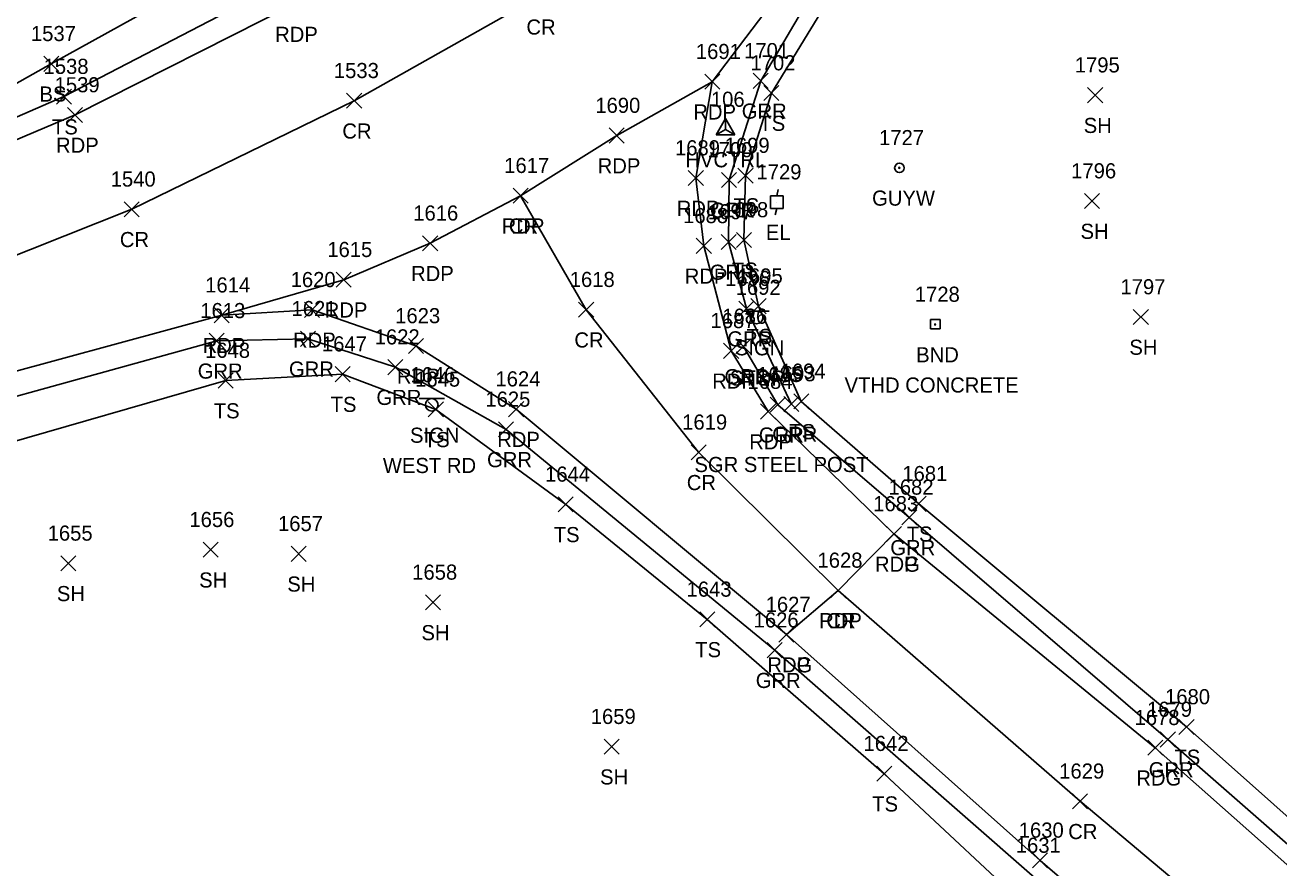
# Model space of a CAD drawing. Extents: x 1629176 to 1637209, y 606063 to 610167.
# Drawn here: x 1629782.2 to 1629948.1, y 606728.3 to 606839.8 of the extents above; entities that cross this region are included whole.
import ezdxf

# ---------------------------------------------------------------- set-up
doc = ezdxf.new("R2010")
doc.units = 0
for name, color, linetype in [('C_A', 7, 'Continuous'), ('C_I', 7, 'Continuous'), ('CPSM', 7, 'Continuous'), ('L_A', 7, 'Continuous'), ('L_I', 7, 'Continuous'), ('L_TIC', 7, 'Continuous'), ('LELB', 7, 'Continuous'), ('M_A', 7, 'Continuous'), ('M_C', 7, 'Continuous'), ('M_I', 7, 'Continuous'), ('MHBP', 7, 'Continuous'), ('P_A', 7, 'Continuous'), ('P_I', 7, 'Continuous'), ('P_TIC', 7, 'Continuous'), ('PET', 7, 'Continuous'), ('PEU', 7, 'Continuous'), ('PRC', 7, 'Continuous'), ('R_A', 7, 'Continuous'), ('R_C', 7, 'Continuous'), ('R_I', 7, 'Continuous'), ('R_TIC', 7, 'Continuous'), ('RGR', 7, 'Continuous'), ('S_A', 7, 'Continuous'), ('S_C', 7, 'Continuous'), ('S_I', 7, 'Continuous'), ('SSGN', 7, 'Continuous'), ('U_A', 7, 'Continuous'), ('U_I', 7, 'Continuous'), ('UEPT', 7, 'Continuous'), ('UPGW', 7, 'Continuous')]:
    doc.layers.add(name, color=color, linetype=linetype)

msp = doc.modelspace()

# ---------------------------------------------------------------- linework, layer by layer
at = {"layer": 'CPSM'}
for p, q in [((1629873.61, 606825.25), (1629874.86, 606827.42)), ((1629876.11, 606825.25), (1629874.86, 606827.42)), ((1629874.86, 606825.97), (1629874.86, 606827.42)), ((1629873.61, 606825.25), (1629874.86, 606825.97)), ((1629873.61, 606825.25), (1629876.11, 606825.25)), ((1629874.86, 606825.97), (1629874.86, 606825.97)), ((1629874.86, 606825.97), (1629876.11, 606825.25))]:
    msp.add_line(p, q, dxfattribs=at)
at = {"layer": 'L_TIC'}
for points in [[(1629784.68, 606833.66), (1629786.68, 606835.66)], [(1629786.68, 606833.66), (1629784.68, 606835.66)], [(1629786.36, 606829.32), (1629788.36, 606831.32)], [(1629788.36, 606829.32), (1629786.36, 606831.32)], [(1629879.93, 606829.79), (1629881.93, 606831.79)], [(1629881.93, 606829.79), (1629879.93, 606831.79)], [(1629922.75, 606829.51), (1629924.75, 606831.51)], [(1629924.75, 606829.51), (1629922.75, 606831.51)], [(1629876.5, 606818.88), (1629878.5, 606820.88)], [(1629878.5, 606818.88), (1629876.5, 606820.88)], [(1629922.33, 606815.51), (1629924.33, 606817.51)], [(1629924.33, 606815.51), (1629922.33, 606817.51)], [(1629876.3, 606810.37), (1629878.3, 606812.37)], [(1629878.3, 606810.37), (1629876.3, 606812.37)], [(1629878.22, 606801.61), (1629880.22, 606803.61)], [(1629880.22, 606801.61), (1629878.22, 606803.61)], [(1629928.79, 606800.18), (1629930.79, 606802.18)], [(1629930.79, 606800.18), (1629928.79, 606802.18)], [(1629807.76, 606791.78), (1629809.76, 606793.78)], [(1629809.76, 606791.78), (1629807.76, 606793.78)], [(1629823.22, 606792.63), (1629825.22, 606794.63)], [(1629825.22, 606792.63), (1629823.22, 606794.63)], [(1629835.55, 606787.97), (1629837.55, 606789.97)], [(1629837.55, 606787.97), (1629835.55, 606789.97)], [(1629883.89, 606789.02), (1629885.89, 606791.02)], [(1629885.89, 606789.02), (1629883.89, 606791.02)], [(1629852.73, 606775.41), (1629854.73, 606777.41)], [(1629854.73, 606775.41), (1629852.73, 606777.41)], [(1629899.42, 606775.48), (1629901.42, 606777.48)], [(1629901.42, 606775.48), (1629899.42, 606777.48)], [(1629805.75, 606769.41), (1629807.75, 606771.41)], [(1629807.75, 606769.41), (1629805.75, 606771.41)], [(1629817.41, 606768.87), (1629819.41, 606770.87)], [(1629819.41, 606768.87), (1629817.41, 606770.87)], [(1629786.94, 606767.61), (1629788.94, 606769.61)], [(1629788.94, 606767.61), (1629786.94, 606769.61)], [(1629835.16, 606762.45), (1629837.16, 606764.45)], [(1629837.16, 606762.45), (1629835.16, 606764.45)], [(1629871.45, 606760.2), (1629873.45, 606762.2)], [(1629873.45, 606760.2), (1629871.45, 606762.2)], [(1629934.83, 606745.98), (1629936.83, 606747.98)], [(1629936.83, 606745.98), (1629934.83, 606747.98)], [(1629858.79, 606743.37), (1629860.79, 606745.37)], [(1629860.79, 606743.37), (1629858.79, 606745.37)], [(1629894.86, 606739.8), (1629896.86, 606741.8)], [(1629896.86, 606739.8), (1629894.86, 606741.8)]]:
    msp.add_lwpolyline(points, dxfattribs=at)
at = {"layer": 'LELB'}
for points in [[(1629537.12, 607012.67), (1629575, 607007.04), (1629623.31, 606998.78), (1629670.49, 606990.16), (1629714.53, 606981.27), (1629760, 606971.03), (1629801.55, 606961.38), (1629838.05, 606950.95), (1629877.99, 606935.18), (1629884.4, 606927.34), (1629887.99, 606913), (1629884.23, 606901.72), (1629876.6, 606890.52), (1629858.53, 606872.94), (1629837.71, 606857.41), (1629816.19, 606845.34), (1629787.36, 606830.32), (1629768.49, 606822.14), (1629743.52, 606814.41), (1629718.72, 606809.85), (1629691.15, 606805.56), (1629666.46, 606804.24), (1629631.78, 606804.97), (1629589.26, 606807.01)], [(1629877.25, 606930.15), (1629884.92, 606913), (1629880.28, 606898.59), (1629867.99, 606890.41), (1629855.23, 606876.92), (1629834.43, 606863.57), (1629813.18, 606849.89), (1629785.68, 606834.66), (1629767.63, 606824.5), (1629742.65, 606817.12), (1629717.54, 606811.78), (1629690.44, 606808.71), (1629665, 606806.93)], [(1630072.99, 606627.47), (1630041.99, 606654.51), (1630010.01, 606681.22), (1629981.64, 606706.28), (1629935.83, 606746.98), (1629900.42, 606776.48), (1629884.89, 606790.02), (1629879.22, 606802.61), (1629877.3, 606811.37), (1629877.5, 606819.88), (1629880.93, 606830.79), (1629891.36, 606847.82), (1629915.71, 606875.42), (1629940.9, 606902.48), (1629963.67, 606912.99), (1630002.21, 606903.33), (1630044.25, 606889.35), (1630091.41, 606872.59)], [(1629974.23, 606671.73), (1629944.56, 606697.88), (1629917.84, 606720.26), (1629895.86, 606740.8), (1629872.45, 606761.2), (1629853.73, 606776.41), (1629836.55, 606788.97), (1629824.22, 606793.63), (1629808.76, 606792.78), (1629777.19, 606783.69), (1629732.57, 606770.35)]]:
    msp.add_lwpolyline(points, dxfattribs=at)
at = {"layer": 'MHBP'}
for p, q in [((1629903.24, 606800.85), (1629901.99, 606800.85)), ((1629901.99, 606800.85), (1629901.99, 606799.6)), ((1629903.24, 606800.85), (1629901.99, 606800.85)), ((1629901.99, 606800.85), (1629901.99, 606799.6)), ((1629903.24, 606799.6), (1629903.24, 606800.85)), ((1629903.24, 606799.6), (1629903.24, 606800.85)), ((1629901.99, 606799.6), (1629903.24, 606799.6)), ((1629901.99, 606799.6), (1629903.24, 606799.6))]:
    msp.add_line(p, q, dxfattribs=at)
msp.add_circle((1629902.59, 606800.19), 0.0833, dxfattribs=at)
at = {"layer": 'P_TIC'}
for points in [[(1629872.11, 606831.29), (1629874.11, 606833.29)], [(1629874.11, 606831.29), (1629872.11, 606833.29)], [(1629872.11, 606831.29), (1629874.11, 606833.29)], [(1629874.11, 606831.29), (1629872.11, 606833.29)], [(1629824.75, 606828.77), (1629826.75, 606830.77)], [(1629826.75, 606828.77), (1629824.75, 606830.77)], [(1629787.82, 606826.89), (1629789.82, 606828.89)], [(1629789.82, 606826.89), (1629787.82, 606828.89)], [(1629859.47, 606824.17), (1629861.47, 606826.17)], [(1629861.47, 606824.17), (1629859.47, 606826.17)], [(1629869.93, 606818.55), (1629871.93, 606820.55)], [(1629871.93, 606818.55), (1629869.93, 606820.55)], [(1629846.76, 606816.22), (1629848.76, 606818.22)], [(1629848.76, 606816.22), (1629846.76, 606818.22)], [(1629846.76, 606816.22), (1629848.76, 606818.22)], [(1629848.76, 606816.22), (1629846.76, 606818.22)], [(1629795.32, 606814.42), (1629797.32, 606816.42)], [(1629797.32, 606814.42), (1629795.32, 606816.42)], [(1629834.79, 606809.93), (1629836.79, 606811.93)], [(1629836.79, 606809.93), (1629834.79, 606811.93)], [(1629870.99, 606809.59), (1629872.99, 606811.59)], [(1629872.99, 606809.59), (1629870.99, 606811.59)], [(1629823.36, 606805.11), (1629825.36, 606807.11)], [(1629825.36, 606805.11), (1629823.36, 606807.11)], [(1629819.17, 606801.13), (1629821.17, 606803.13)], [(1629821.17, 606801.13), (1629819.17, 606803.13)], [(1629855.43, 606801.15), (1629857.43, 606803.15)], [(1629857.43, 606801.15), (1629855.43, 606803.15)], [(1629807.22, 606800.42), (1629809.22, 606802.42)], [(1629809.22, 606800.42), (1629807.22, 606802.42)], [(1629807.22, 606800.42), (1629809.22, 606802.42)], [(1629809.22, 606800.42), (1629807.22, 606802.42)], [(1629832.92, 606796.36), (1629834.92, 606798.36)], [(1629834.92, 606796.36), (1629832.92, 606798.36)], [(1629874.61, 606795.71), (1629876.61, 606797.71)], [(1629876.61, 606795.71), (1629874.61, 606797.71)], [(1629846.17, 606788), (1629848.17, 606790)], [(1629848.17, 606788), (1629846.17, 606790)], [(1629879.51, 606787.68), (1629881.51, 606789.68)], [(1629881.51, 606787.68), (1629879.51, 606789.68)], [(1629870.31, 606782.29), (1629872.31, 606784.29)], [(1629872.31, 606782.29), (1629870.31, 606784.29)], [(1629896.14, 606771.5), (1629898.14, 606773.5)], [(1629898.14, 606771.5), (1629896.14, 606773.5)], [(1629896.14, 606771.5), (1629898.14, 606773.5)], [(1629898.14, 606771.5), (1629896.14, 606773.5)], [(1629888.77, 606764.03), (1629890.77, 606766.03)], [(1629890.77, 606764.03), (1629888.77, 606766.03)], [(1629888.77, 606764.03), (1629890.77, 606766.03)], [(1629890.77, 606764.03), (1629888.77, 606766.03)], [(1629881.91, 606758.19), (1629883.91, 606760.19)], [(1629883.91, 606758.19), (1629881.91, 606760.19)], [(1629881.91, 606758.19), (1629883.91, 606760.19)], [(1629883.91, 606758.19), (1629881.91, 606760.19)], [(1629930.71, 606743.23), (1629932.71, 606745.23)], [(1629932.71, 606743.23), (1629930.71, 606745.23)], [(1629920.75, 606736.15), (1629922.75, 606738.15)], [(1629922.75, 606736.15), (1629920.75, 606738.15)], [(1629915.47, 606728.34), (1629917.47, 606730.34)], [(1629917.47, 606728.34), (1629915.47, 606730.34)]]:
    msp.add_lwpolyline(points, dxfattribs=at)
at = {"layer": 'PET'}
for points in [[(1629871.33, 606945.94), (1629880.42, 606941.23), (1629888.42, 606926.9), (1629889.97, 606912.21), (1629888.08, 606901.04), (1629880.59, 606887.29), (1629861.33, 606870.19), (1629839.75, 606855.53), (1629817.8, 606842.55), (1629788.82, 606827.89), (1629769.68, 606819.82), (1629744.49, 606811.9), (1629719.68, 606806.2), (1629691.7, 606802.76), (1629667.08, 606801.51), (1629631.79, 606801.55), (1629588.78, 606803.44)], [(1629587.14, 606776.73), (1629623.38, 606774.29), (1629651.95, 606774.51), (1629678.56, 606774.68), (1629701.14, 606776.11), (1629724.19, 606779.3), (1629746.4, 606783.99), (1629772.89, 606791.82), (1629808.22, 606801.42), (1629824.36, 606806.11), (1629835.79, 606810.93), (1629847.76, 606817.22), (1629860.47, 606825.17), (1629873.11, 606832.29), (1629887.14, 606850.82), (1629912.73, 606877.94), (1629938.57, 606904.89), (1629947.79, 606913.74), (1629954.28, 606917.5), (1629965.2, 606918.43)], [(1629808.22, 606801.42), (1629820.17, 606802.13), (1629833.92, 606797.36), (1629847.17, 606789), (1629882.91, 606759.19), (1629889.77, 606765.03), (1629897.14, 606772.5), (1629880.51, 606788.68), (1629875.61, 606796.71), (1629871.99, 606810.59), (1629870.93, 606819.55), (1629873.11, 606832.29)]]:
    msp.add_lwpolyline(points, dxfattribs=at)
at = {"layer": 'PEU'}
for points in [[(1630069.19, 606623.55), (1630038.4, 606651.5), (1630007.06, 606677.99), (1629977.76, 606703.39), (1629931.71, 606744.23), (1629897.14, 606772.5)], [(1629882.91, 606759.19), (1629916.47, 606729.34), (1629944.44, 606705.22), (1629977.31, 606676.19)]]:
    msp.add_lwpolyline(points, dxfattribs=at)
at = {"layer": 'PRC'}
for points in [[(1629930.37, 606928.51), (1629922.33, 606915.08), (1629903.69, 606892.32), (1629888.42, 606875.5), (1629871.3, 606859.39), (1629850.1, 606843.52), (1629825.75, 606829.77), (1629796.32, 606815.42), (1629774.04, 606806.57), (1629748.19, 606798.61), (1629722.01, 606792.8), (1629693.98, 606789.27), (1629667.56, 606787.71), (1629632.27, 606787.81), (1629586.9, 606789.65)], [(1629847.76, 606817.22), (1629856.43, 606802.15), (1629871.31, 606783.29), (1629889.77, 606765.03), (1629921.75, 606737.15), (1629950.99, 606712.6), (1629983.98, 606682.75), (1630026.35, 606648.49), (1630062.55, 606615.61)]]:
    msp.add_lwpolyline(points, dxfattribs=at)
at = {"layer": 'R_TIC'}
for points in [[(1629878.52, 606831.4), (1629880.52, 606833.4)], [(1629880.52, 606831.4), (1629878.52, 606833.4)], [(1629874.33, 606818.3), (1629876.33, 606820.3)], [(1629876.33, 606818.3), (1629874.33, 606820.3)], [(1629874.27, 606810.1), (1629876.27, 606812.1)], [(1629876.27, 606810.1), (1629874.27, 606812.1)], [(1629876.62, 606801.29), (1629878.62, 606803.29)], [(1629878.62, 606801.29), (1629876.62, 606803.29)], [(1629806.56, 606797.03), (1629808.56, 606799.03)], [(1629808.56, 606797.03), (1629806.56, 606799.03)], [(1629818.63, 606797.3), (1629820.63, 606799.3)], [(1629820.63, 606797.3), (1629818.63, 606799.3)], [(1629876.23, 606796.29), (1629878.23, 606798.29)], [(1629878.23, 606796.29), (1629876.23, 606798.29)], [(1629830.2, 606793.55), (1629832.2, 606795.55)], [(1629832.2, 606793.55), (1629830.2, 606795.55)], [(1629880.78, 606788.58), (1629882.78, 606790.58)], [(1629882.78, 606788.58), (1629880.78, 606790.58)], [(1629882.56, 606788.68), (1629884.56, 606790.68)], [(1629884.56, 606788.68), (1629882.56, 606790.68)], [(1629844.84, 606785.32), (1629846.84, 606787.32)], [(1629846.84, 606785.32), (1629844.84, 606787.32)], [(1629898.17, 606773.69), (1629900.17, 606775.69)], [(1629900.17, 606773.69), (1629898.17, 606775.69)], [(1629880.37, 606756.13), (1629882.37, 606758.13)], [(1629882.37, 606756.13), (1629880.37, 606758.13)], [(1629932.36, 606744.32), (1629934.36, 606746.32)], [(1629934.36, 606744.32), (1629932.36, 606746.32)]]:
    msp.add_lwpolyline(points, dxfattribs=at)
at = {"layer": 'RGR'}
for points in [[(1629883.56, 606789.68), (1629877.62, 606802.29), (1629875.27, 606811.1), (1629875.33, 606819.3), (1629879.52, 606832.4), (1629889.43, 606849.18), (1629913.53, 606877.22), (1629938.73, 606904.49), (1629948.22, 606912.98), (1629955.15, 606916.34), (1629964.74, 606917.13), (1630002.73, 606905.78), (1630044.87, 606891.43), (1630091.95, 606875)], [(1629610.69, 606767.66), (1629614.78, 606771.08), (1629618.2, 606772.52), (1629623.02, 606773.09), (1629651.93, 606771.73), (1629678.65, 606772.42), (1629701.28, 606773.86), (1629724.79, 606776.82), (1629746.85, 606781.44), (1629773.74, 606788.69), (1629807.56, 606798.03), (1629819.63, 606798.3), (1629831.2, 606794.55), (1629845.84, 606786.32), (1629881.37, 606757.13), (1629915.43, 606727.34), (1629943.21, 606703.31), (1629976.52, 606673.99)], [(1630071, 606625.42), (1630039.64, 606652.97), (1630008.64, 606679.73), (1629979.55, 606704.95), (1629933.36, 606745.32), (1629899.17, 606774.69), (1629881.78, 606789.58), (1629877.23, 606797.29)]]:
    msp.add_lwpolyline(points, dxfattribs=at)
at = {"layer": 'SSGN'}
for p, q in [((1629877.32, 606801.96), (1629880.65, 606801.96)), ((1629878.97, 606801.13), (1629878.97, 606801.13)), ((1629834.35, 606790.4), (1629837.68, 606790.4)), ((1629836, 606789.57), (1629836, 606789.57))]:
    msp.add_line(p, q, dxfattribs=at)
for centre in [(1629878.97, 606801.13), (1629836, 606789.57)]:
    msp.add_circle(centre, 0.833, dxfattribs=at)
at = {"layer": 'UEPT'}
for p, q in [((1629881.83, 606818.04), (1629881.66, 606817.21)), ((1629880.83, 606815.54), (1629880.83, 606817.21)), ((1629880.83, 606817.21), (1629882.49, 606817.21)), ((1629881.66, 606816.37), (1629881.66, 606816.37)), ((1629882.49, 606817.21), (1629882.49, 606815.54)), ((1629882.49, 606815.54), (1629880.83, 606815.54)), ((1629881.41, 606814.71), (1629881.66, 606815.54))]:
    msp.add_line(p, q, dxfattribs=at)
at = {"layer": 'UPGW'}
for radius in [0.625, 0.0833]:
    msp.add_circle((1629897.86, 606820.9), radius, dxfattribs=at)

# ---------------------------------------------------------------- texts
at = {"layer": 'C_A'}
msp.add_text('HVCTRL', height=2, dxfattribs=at).set_placement((1629869.55, 606820.97))
at = {"layer": 'C_I'}
msp.add_text('106', height=2, dxfattribs=at).set_placement((1629872.93, 606828.97))
at = {"layer": 'L_A'}
for s, p in [('BS', (1629784.12, 606829.66)), ('TS', (1629879.34, 606825.79)), ('TS', (1629785.77, 606825.32)), ('SH', (1629922.24, 606825.51)), ('TS', (1629875.91, 606814.88)), ('SH', (1629921.82, 606811.51)), ('TS', (1629875.71, 606806.37)), ('TS', (1629877.63, 606797.61)), ('SH', (1629928.28, 606796.18)), ('TS', (1629807.17, 606787.78)), ('TS', (1629822.63, 606788.63)), ('TS', (1629883.3, 606785.02)), ('TS', (1629834.96, 606783.97)), ('TS', (1629852.14, 606771.41)), ('TS', (1629898.83, 606771.48)), ('SH', (1629805.24, 606765.41)), ('SH', (1629816.9, 606764.87)), ('SH', (1629786.42, 606763.61)), ('SH', (1629834.64, 606758.45)), ('TS', (1629870.86, 606756.2)), ('TS', (1629934.24, 606741.98)), ('SH', (1629858.27, 606739.37)), ('TS', (1629894.27, 606735.8))]:
    msp.add_text(s, height=2, dxfattribs=at).set_placement(p)
at = {"layer": 'L_I'}
for s, p in [('1537', (1629782.99, 606837.66)), ('1538', (1629784.66, 606833.32)), ('1702', (1629878.16, 606833.79)), ('1795', (1629921.06, 606833.51)), ('1699', (1629874.75, 606822.88)), ('1796', (1629920.58, 606819.51)), ('1698', (1629874.56, 606814.37)), ('1695', (1629876.48, 606805.61)), ('1797', (1629927.1, 606804.18)), ('1647', (1629821.48, 606796.63)), ('1648', (1629806.02, 606795.78)), ('1694', (1629882.15, 606793.02)), ('1645', (1629833.81, 606791.97)), ('1644', (1629850.99, 606779.41)), ('1681', (1629898.25, 606779.48)), ('1656', (1629803.95, 606773.41)), ('1657', (1629815.67, 606772.87)), ('1655', (1629785.2, 606771.61)), ('1658', (1629833.42, 606766.45)), ('1643', (1629869.71, 606764.2)), ('1680', (1629933, 606749.98)), ('1659', (1629857.04, 606747.37)), ('1642', (1629893.12, 606743.8))]:
    msp.add_text(s, height=2, dxfattribs=at).set_placement(p)
at = {"layer": 'M_A'}
msp.add_text('BND', height=2, dxfattribs=at).set_placement((1629900.08, 606795.19))
at = {"layer": 'M_C'}
msp.add_text('VTHD CONCRETE', height=2, dxfattribs=at).set_placement((1629890.61, 606791.19))
at = {"layer": 'M_I'}
msp.add_text('1728', height=2, dxfattribs=at).set_placement((1629899.9, 606803.19))
at = {"layer": 'P_A'}
for s, p in [('RDP', (1629815.29, 606837.55)), ('CR', (1629848.53, 606838.52)), ('RDP', (1629870.6, 606827.29)), ('RDP', (1629870.6, 606827.29)), ('CR', (1629824.18, 606824.77)), ('RDP', (1629786.31, 606822.89)), ('RDP', (1629857.95, 606820.17)), ('RDP', (1629868.41, 606814.55)), ('RDP', (1629845.25, 606812.22)), ('CR', (1629846.2, 606812.22)), ('CR', (1629794.75, 606810.42)), ('RDP', (1629833.27, 606805.93)), ('RDP', (1629869.47, 606805.59)), ('RDP', (1629821.85, 606801.11)), ('RDP', (1629805.7, 606796.42)), ('RDP', (1629805.7, 606796.42)), ('RDP', (1629817.65, 606797.13)), ('CR', (1629854.87, 606797.15)), ('RDP', (1629831.4, 606792.36)), ('RDP', (1629873.1, 606791.71)), ('RDP', (1629844.66, 606784)), ('RDP', (1629878, 606783.68)), ('CR', (1629869.74, 606778.29)), ('RDG', (1629894.63, 606767.5)), ('RDP', (1629894.63, 606767.5)), ('RDP', (1629887.25, 606760.03)), ('CR', (1629888.2, 606760.03)), ('RDG', (1629880.4, 606754.19)), ('RDP', (1629880.4, 606754.19)), ('RDG', (1629929.2, 606739.23)), ('CR', (1629920.19, 606732.15))]:
    msp.add_text(s, height=2, dxfattribs=at).set_placement(p)
at = {"layer": 'P_I'}
for s, p in [('1691', (1629870.94, 606835.29)), ('1691', (1629870.94, 606835.29)), ('1533', (1629823.06, 606832.77)), ('1539', (1629786.12, 606830.89)), ('1690', (1629857.64, 606828.17)), ('1689', (1629868.18, 606822.55)), ('1617', (1629845.59, 606820.22)), ('1617', (1629845.59, 606820.22)), ('1540', (1629793.54, 606818.42)), ('1616', (1629833.56, 606813.93)), ('1688', (1629869.25, 606813.59)), ('1615', (1629822.19, 606809.11)), ('1614', (1629806.04, 606804.42)), ('1614', (1629806.04, 606804.42)), ('1620', (1629817.34, 606805.13)), ('1618', (1629854.26, 606805.15)), ('1623', (1629831.17, 606800.36)), ('1687', (1629872.87, 606799.71)), ('1624', (1629844.43, 606792)), ('1684', (1629877.77, 606791.68)), ('1619', (1629869.13, 606786.29)), ('1683', (1629894.4, 606775.5)), ('1683', (1629894.4, 606775.5)), ('1628', (1629887.03, 606768.03)), ('1628', (1629887.03, 606768.03)), ('1627', (1629880.17, 606762.19)), ('1627', (1629880.17, 606762.19)), ('1678', (1629928.97, 606747.23)), ('1629', (1629919, 606740.15)), ('1630', (1629913.65, 606732.34))]:
    msp.add_text(s, height=2, dxfattribs=at).set_placement(p)
at = {"layer": 'R_A'}
for p in [(1629877.01, 606827.4), (1629872.81, 606814.3), (1629872.76, 606806.1), (1629875.11, 606797.29), (1629805.05, 606793.03), (1629817.12, 606793.3), (1629874.72, 606792.29), (1629828.69, 606789.55), (1629879.27, 606784.58), (1629881.05, 606784.68), (1629843.32, 606781.32), (1629896.66, 606769.69), (1629878.86, 606752.13), (1629930.84, 606740.32)]:
    msp.add_text('GRR', height=2, dxfattribs=at).set_placement(p)
at = {"layer": 'R_C'}
msp.add_text('SGR STEEL POST', height=2, dxfattribs=at).set_placement((1629870.75, 606780.68))
at = {"layer": 'R_I'}
for s, p in [('1701', (1629877.32, 606835.4)), ('1700', (1629872.47, 606822.3)), ('1697', (1629872.53, 606814.1)), ('1696', (1629874.82, 606805.29)), ('1613', (1629805.39, 606801.03)), ('1621', (1629817.46, 606801.3)), ('1686', (1629874.43, 606800.29)), ('1622', (1629828.46, 606797.55)), ('1693', (1629880.82, 606792.68)), ('1685', (1629879.04, 606792.58)), ('1625', (1629843.1, 606789.32)), ('1682', (1629896.43, 606777.69)), ('1626', (1629878.58, 606760.13)), ('1679', (1629930.61, 606748.32)), ('1631', (1629913.26, 606730.34))]:
    msp.add_text(s, height=2, dxfattribs=at).set_placement(p)
at = {"layer": 'S_A'}
for p in [(1629876.1, 606796.11), (1629833.13, 606784.55)]:
    msp.add_text('SIGN', height=2, dxfattribs=at).set_placement(p)
at = {"layer": 'S_C'}
for s, p in [('STOP', (1629875.43, 606792.11)), ('WEST RD', (1629829.54, 606780.55))]:
    msp.add_text(s, height=2, dxfattribs=at).set_placement(p)
at = {"layer": 'S_I'}
for s, p in [('1692', (1629876.21, 606804.11)), ('1646', (1629833.18, 606792.55))]:
    msp.add_text(s, height=2, dxfattribs=at).set_placement(p)
at = {"layer": 'U_A'}
for s, p in [('GUYW', (1629894.25, 606815.9)), ('EL', (1629880.2, 606811.37))]:
    msp.add_text(s, height=2, dxfattribs=at).set_placement(p)
at = {"layer": 'U_I'}
for s, p in [('1727', (1629895.17, 606823.9)), ('1729', (1629878.96, 606819.37))]:
    msp.add_text(s, height=2, dxfattribs=at).set_placement(p)

doc.saveas('drawing.dxf')
